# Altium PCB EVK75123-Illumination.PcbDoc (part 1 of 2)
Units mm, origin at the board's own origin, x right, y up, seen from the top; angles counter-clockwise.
Board outline 80 x 50 mm, 4 copper layers (Top Layer, GND, VCC, Bottom Layer), stack 0.976 mm thick; 91 components, 44 nets, 247 pads, 1773 vias.
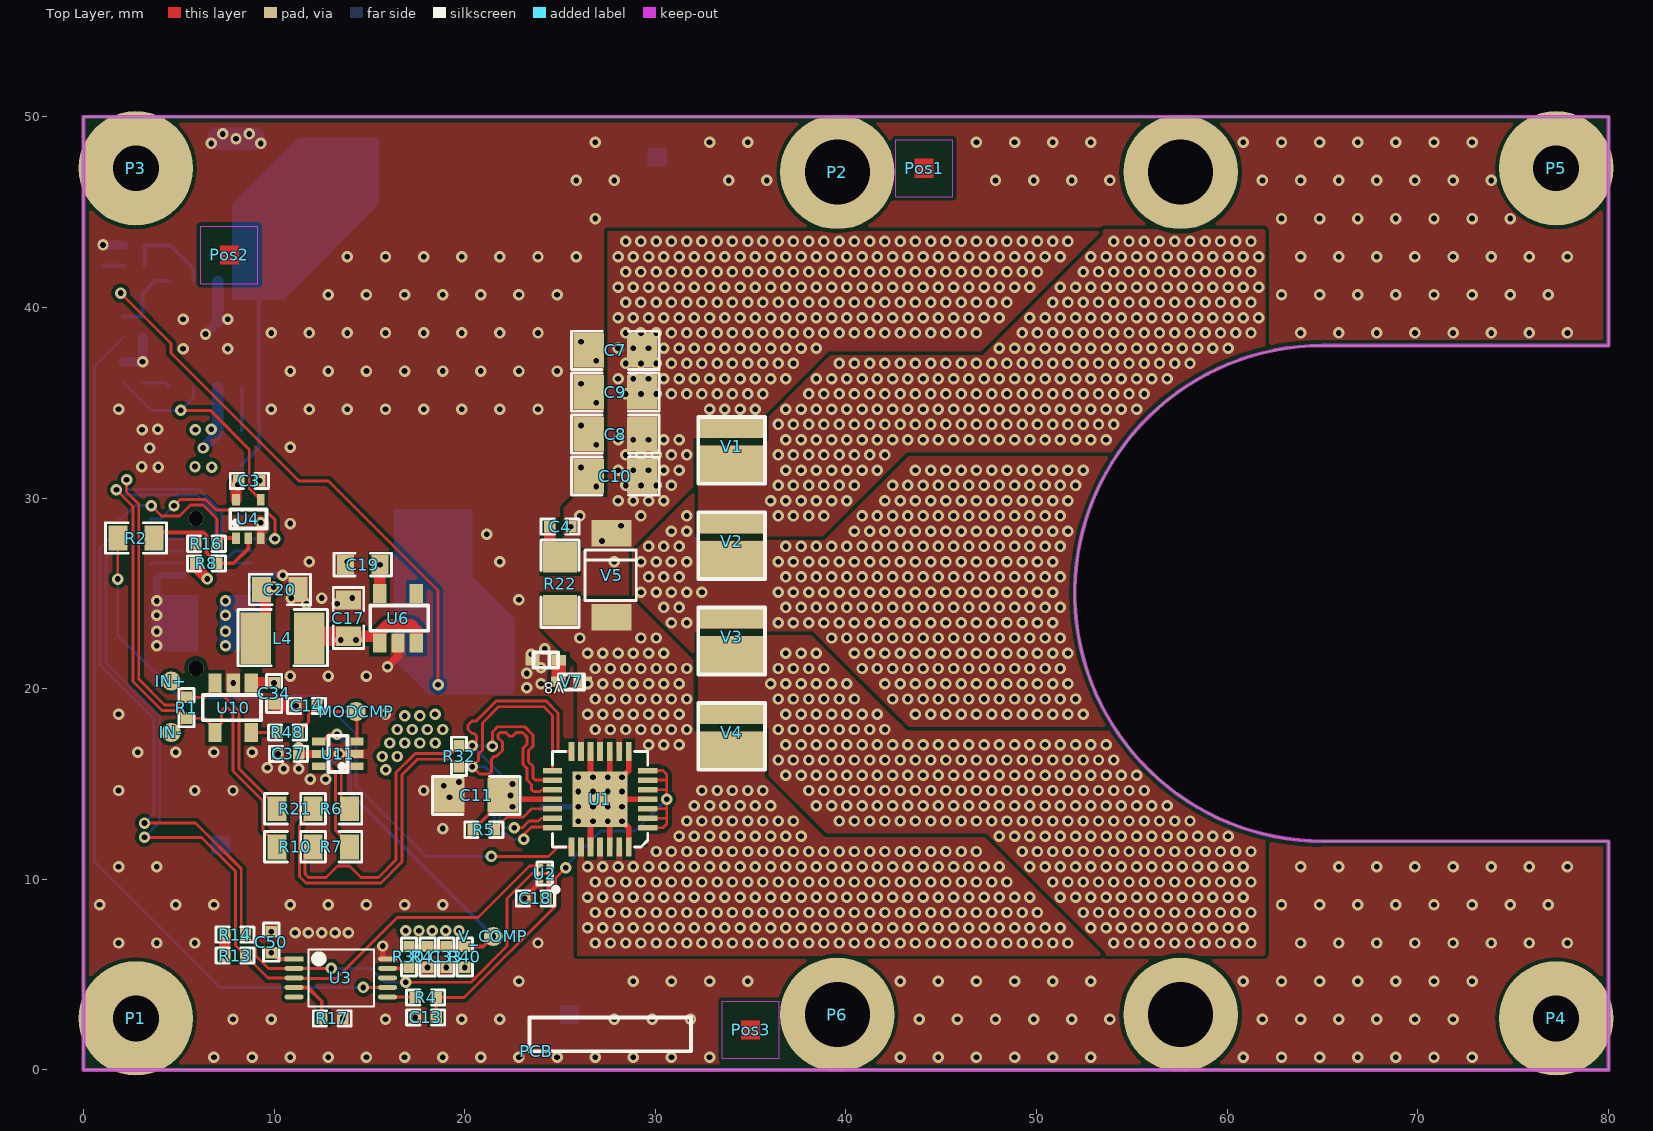
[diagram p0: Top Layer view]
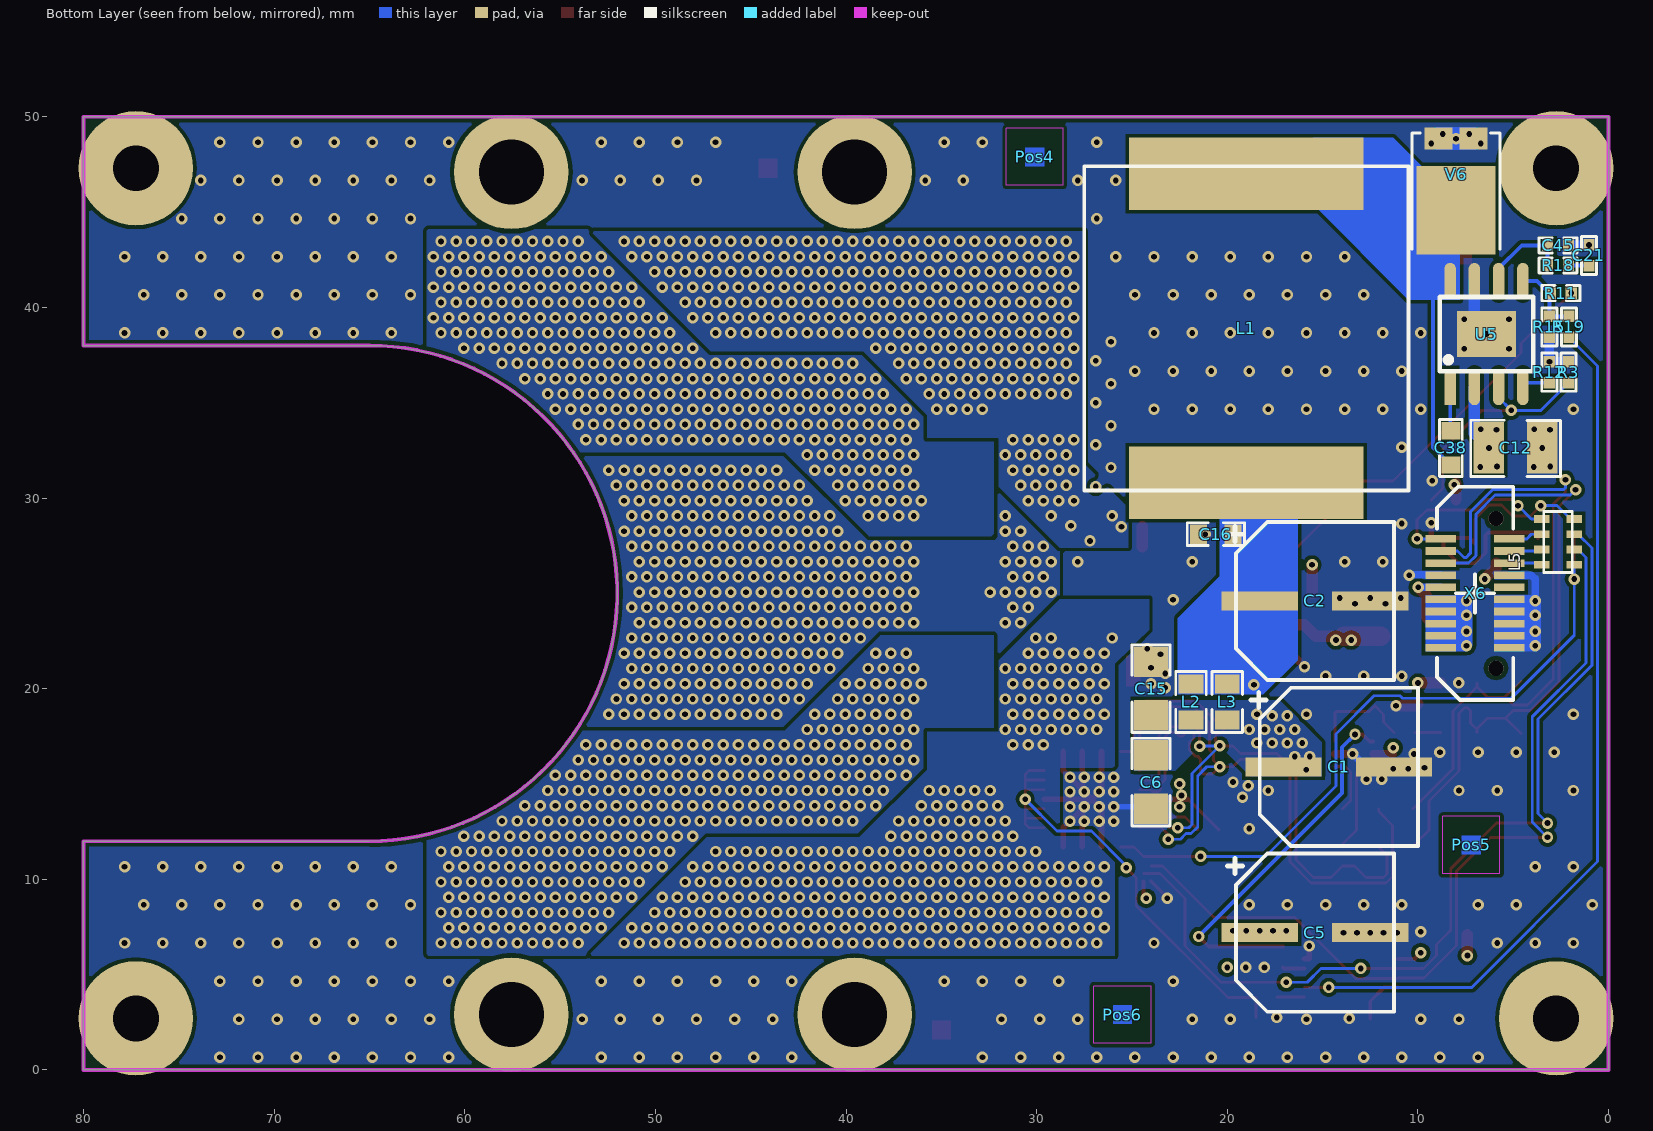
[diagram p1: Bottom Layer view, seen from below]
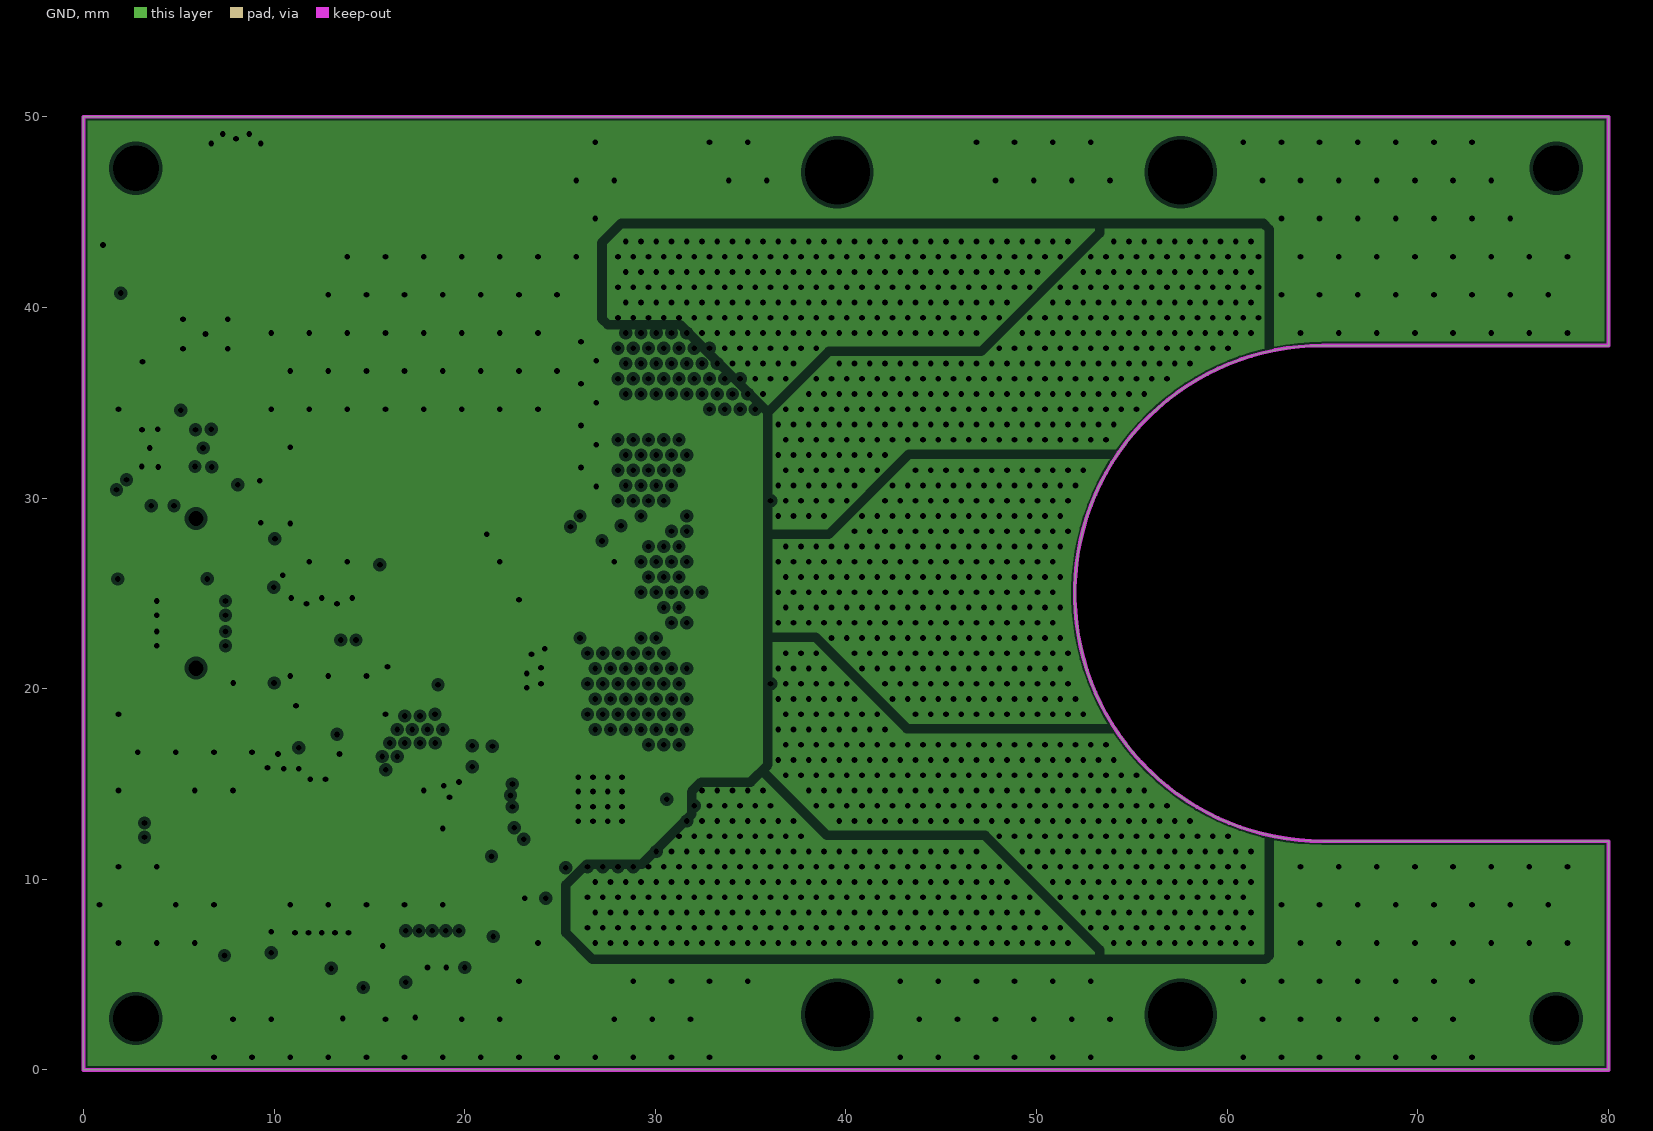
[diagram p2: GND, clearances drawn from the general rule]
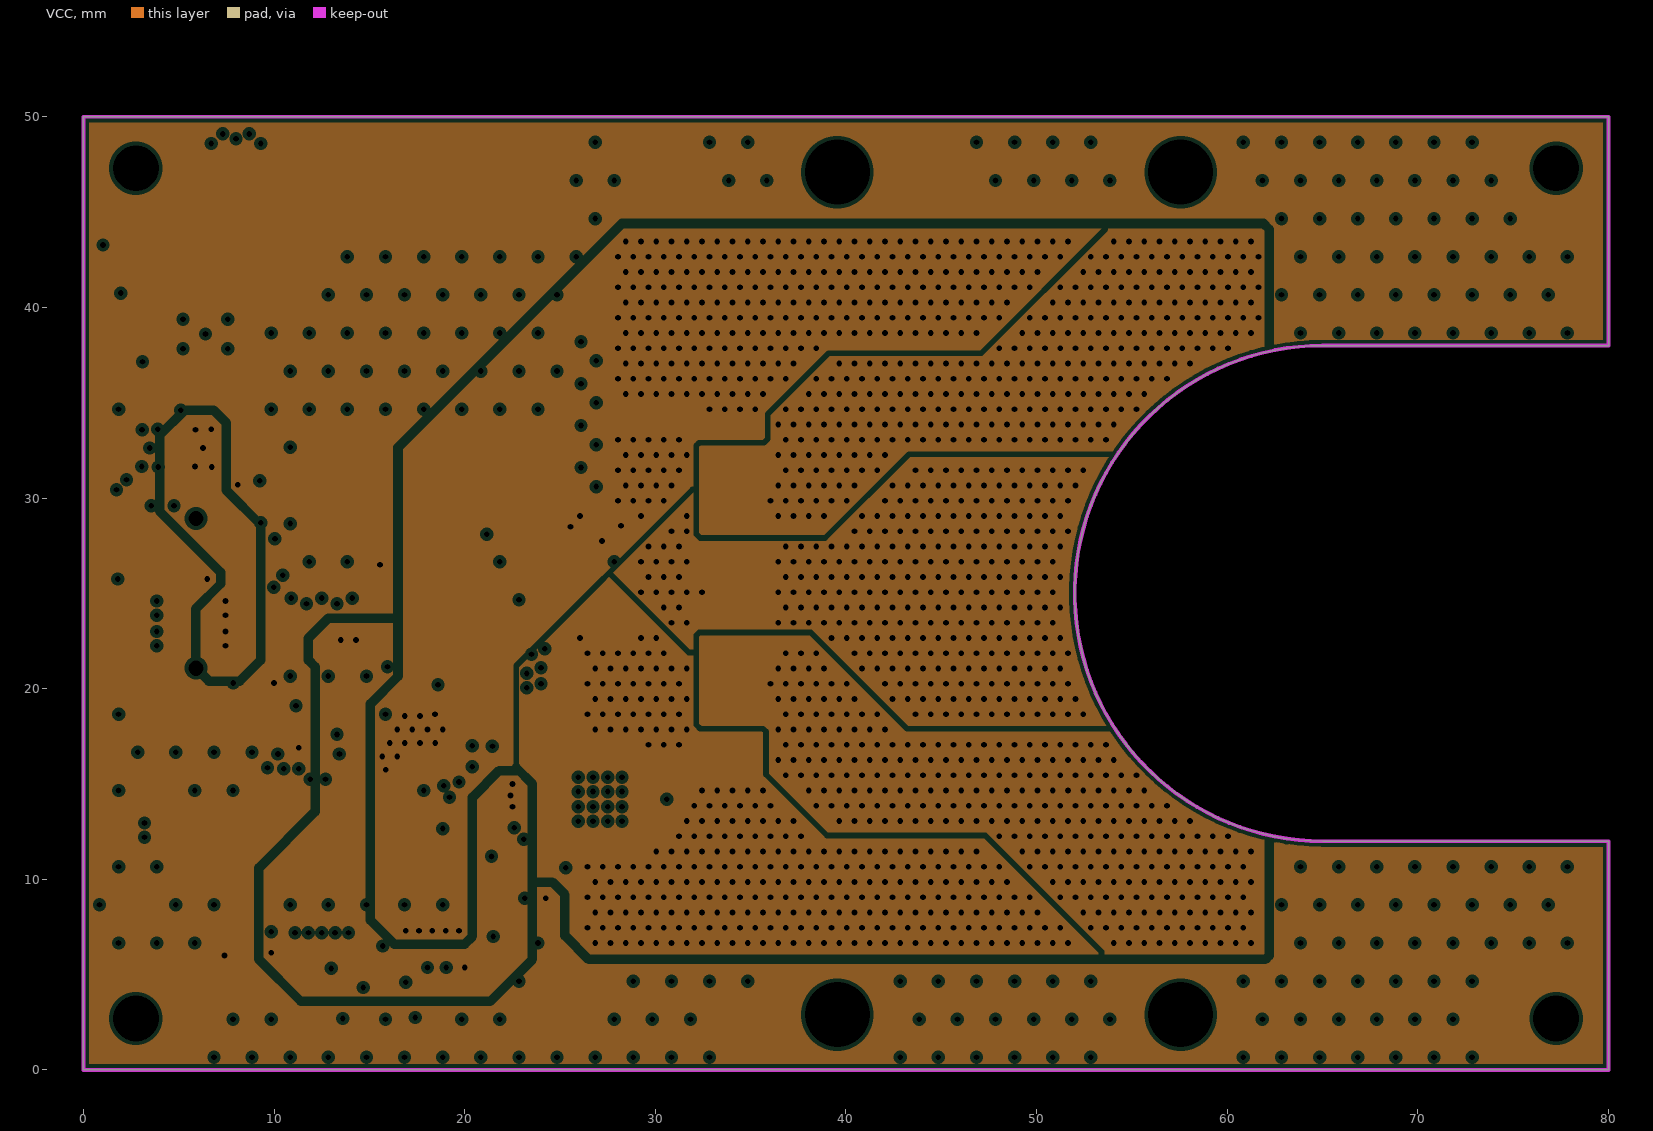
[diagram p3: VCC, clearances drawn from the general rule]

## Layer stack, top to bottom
Top Solder: solder mask 0.05, Solder Resist, Dk 3.5
Top Layer: signal copper 0.039
Dielectric1: prepreg 0.117, FR-4, Dk 4.3
GND: plane copper 0.032, net (Multiple Nets)
Dielectric3: core 0.6, FR-4, Dk 4.47
VCC: plane copper 0.032, net (Multiple Nets)
Dielectric2: prepreg 0.117, FR-4, Dk 4.3
Bottom Layer: signal copper 0.039
Bottom Solder: solder mask 0.05, Solder Resist, Dk 3.5

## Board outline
0,0 0,50 80,50 80,38 65,38 ccw(c65,25) 65,12 80,12 80,0

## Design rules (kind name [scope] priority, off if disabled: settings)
AssemblyTestPointUsage [not (NetPinCount = 1)] p1: allowmultiple=TRUE
AssemblyTestpoint AssemblyTestpoint_Pad [(IsPad And (OnTopLayer)OR (OnBottom))] p1: testpointundercomponent=TRUE minsize=0.8 maxsize=3 preferedsize=0.8 minholesize=0 maxholesize=0 preferedholesize=0 testpointgrid=0.025 usegrid=FALSE gridtolerance=0 allowsidebottom=TRUE minspacing=2.54
AssemblyTestpoint AssemblyTestpoint_Via [(IsVia)] p2: testpointundercomponent=TRUE minsize=0.6 maxsize=0.8 preferedsize=0.8 minholesize=0 maxholesize=0.3 preferedholesize=0.3 testpointgrid=0.025 usegrid=FALSE gridtolerance=0 allowsidebottom=TRUE minspacing=2.54
AssemblyTestpoint AssemblyTestpoint_THT [(IsPad And OnMultiLayer)] p3: testpointundercomponent=TRUE minsize=0.5 maxsize=5 preferedsize=1.524 minholesize=0 maxholesize=3 preferedholesize=0.813 testpointgrid=0.025 usegrid=FALSE gridtolerance=0 allowsidetop=TRUE allowsidebottom=TRUE
AssemblyTestpoint [All] p4: testpointundercomponent=TRUE minsize=1.016 maxsize=2.54 preferedsize=1.524 minholesize=0 maxholesize=1.016 preferedholesize=0.813 testpointgrid=0.025 usegrid=TRUE gridtolerance=0 allowsidetop=TRUE allowsidebottom=TRUE
Clearance Clearance_Hole [All vs not PadIsPlated] p1: gap=0.23
Clearance Clearance_poly [inpolygon] p2: gap=0.2
Clearance [All] p3: gap=0.15
ComponentClearance [not ((InComponent('R7') OR InComponent('R10') OR InComponent('R21') OR InComponent('R6')))] p1: gap=0.1 collisioncheckmode=3 verticalgap=0.1 showdistances=FALSE
DiffPairsRouting [All] p1: maxlimit=0.15 minlimit=0.15 mostfreqgap=0.15 toplayer_minwidth=0.15 toplayer_maxwidth=0.15 toplayer_prefwidth=0.15 bottomlayer_minwidth=0.15 bottomlayer_maxwidth=0.15 bottomlayer_prefwidth=0.15 maxuncoupledlength=17
HoleSize [All] p1: absolutevalues=TRUE maxlimit=3.5 minlimit=0.3 maxpercent=80.000 minpercent=20.000
MatchedLengths MOD [InxSignalClass('MOD')] p1: tolerance=0.2 checknetsindiffpair=FALSE checkdiffpairvsdiffpair=TRUE checkxsignals=TRUE checkothers=TRUE
MatchedLengths MOD_DC [InxSignalClass('All xSignals')] p2: tolerance=0.2 checknetsindiffpair=TRUE checkdiffpairvsdiffpair=FALSE checkxsignals=FALSE checkothers=FALSE
MinimumSolderMaskSliver [All vs IsVia] p1: minsoldermaskwidth=0.1
PlaneClearance PlaneClearance_MH [InPadClass('MH')] p1: clearance=0.5
PlaneClearance [All] p2: clearance=0.2
PlaneConnect [All] p1: planeconnectstyle=Direct reliefexpansion=0.5 reliefentries=4 reliefconductorwidth=0.3 reliefairgap=0.2
PolygonConnect [All] p1: connectstyle=Direct reliefconductorwidth=0.3 reliefentries=4 polygonreliefangle="90 Angle" airgapwidth=0.254
RoutingVias [All] p1: holewidth=0.3 width=0.6 viastyle="Through Hole" minholewidth=0.3 minwidth=0.6 maxholewidth=0.3 maxwidth=0.6
SilkToSolderMaskClearance SilkscreenOverComponentPads [IsPad] p1: minsilkscreentomaskgap=0.254 clearancetoexposedcopper=TRUE
SolderMaskExpansion SolderMaskExpansion_Via [IsVia] p1: expansion=-0.05
SolderMaskExpansion SolderMaskExpansion_ALL [All] p2: expansion=0.05
UnConnectedPin [All] p1:
ViasUnderSMD [All] p1: allowed=TRUE
Width [All] p1: maxlimit=3 minlimit=0.15 preferedwidth=0.15
21 further rules are at their usual default settings.

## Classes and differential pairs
component class U_Power: 24V C1 C2 C5 C6 C12 C15 C16 C19 C21 C38 C45 L1 L2 L3 P1 P2 P3 P4 P5 P6 Pos1 Pos2 Pos3 Pos4 Pos5 Pos6 R3 R11 R12 R15 R18 R19 U5 U6 V6
net class DIFF100: IN_N IN_P MOD1_N MOD1_P MOD_N MOD_P
component class EVK75123-Illumination: C3 C14 C17 C18 C20 C33 C34 C37 C50 IN+ IN- L4 L5 MODCMP PCB R1 R2 R6 R7 R8 R10 R13 R14 R16 R17 R21 R30 R40 R41 R48 U2 U3 U4 U10 U11 V_COMP X6
net class <Power>: 3V3 5V0 17V 24V GND VLD
net class <Hi-Speed>: IN_N IN_P MOD1_N MOD1_P MOD_N MOD_P NAMS2 NAMS3 NAMS4 NAMS5 NAMS6 NAMS7 NAMS8 NAMS9 NAMS10
component class U_Laserdriver: C4 C7 C8 C9 C10 C11 C13 R4 R5 R22 R32 U1 V1 V2 V3 V4 V5 V7 V8
pad class MH: Free-H0 Free-H1 P1-1 P2-1 P3-1 P4-1 P5-1 P6-1
differential pair MOD: +MOD_P -MOD_N
differential pair MOD1: +MOD1_P -MOD1_N
differential pair IN: +IN_P -IN_N

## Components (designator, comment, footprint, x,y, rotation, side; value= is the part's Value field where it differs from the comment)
C1 "Polarized Capicator" ELKO_SMD-8x7 14.15,15.9 r0 bottom
C2 "Polarized Capicator" ELKO_SMD-8x7 15.4,24.6 r0 bottom
C3 "Capacitor non-polarized" 0402 8.7,30.9 r0 top
C4 "Capacitor non-polarized" 0402 25,28.5 r0 top
C5 "Polarized Capicator" ELKO_SMD-8x7 15.4,7.2 r0 bottom
C6 "Capacitor non-polarized" 1206 24,15.1 r270 bottom
C7 "Capacitor non-polarized" 1206 27.9,37.75 r0 top
C8 "Capacitor non-polarized" 1206 27.9,33.35 r0 top
C9 "Capacitor non-polarized" 1206 27.9,35.55 r0 top
C10 "Capacitor non-polarized" 1206 27.9,31.15 r0 top
C11 "Capacitor non-polarized" 1206 20.6,14.4 r0 top
C12 "Capacitor non-polarized" 1210 4.875,32.625 r0 bottom
C13 "Capacitor non-polarized" 0402 17.95,2.75 r0 top
C14 "Capacitor non-polarized" 0402 11.7,19.1 r0 top
C15 "Capacitor non-polarized" 1206 24,20 r270 bottom
C16 "Capacitor non-polarized" 0603 20.6,28.1 r0 bottom
C17 "Capacitor non-polarized" 0805 13.9,23.7 r270 top
C18 "Capacitor non-polarized" 0402 23.7,9 r0 top
C19 "Capacitor non-polarized" 0603 14.65,26.5 r0 top
C20 "Capacitor non-polarized" 0805 10.3,25.2 r180 top
C21 "Capacitor non-polarized" 0402 1.025,42.725 r270 bottom
C33 "Capacitor non-polarized" 0402 19.025,5.925 r270 top
C34 "Capacitor non-polarized" 0402 10,19.75 r270 top
C37 "Capacitor non-polarized" 0402 10.75,16.575 r180 top
C38 "Capacitor non-polarized" 0603 8.275,32.625 r90 bottom
C45 "Capacitor non-polarized" 0402 2.65,43.25 r0 bottom
C50 "Capacitor non-polarized" 0402 9.85,6.7 r270 top
IN+ "Test Pad" PAD_1mm_SMD 4.6,20.4 r0 top
IN- "Test Pad" PAD_1mm_SMD 4.6,17.7 r0 top
L1 "Inductor" VIS-IHLP-6767DZ 19,38.9 r270 bottom
L2 "Ferrite" 0805 21.9,19.3 r270 bottom
L3 "Ferrite" 0805 20,19.3 r270 bottom
L4 "Inductor" 1210 10.45,22.65 r0 top
L5 "Ferrite" 1206_FB-array 2.65,27.7 r90 bottom
MODCMP "Test Pad" PAD_1mm_SMD 14.3,18.8 r90 top
P1 "Test Pad" PAD_M2-5x5#1 2.75,2.7 r270 top locked
P2 "Test Pad" PAD_M2-5x5#2 39.55,47.1 r270 top locked
P3 "Test Pad" PAD_M2-5x5#1 2.75,47.3 r270 top locked
P4 "Test Pad" PAD_M2-5x5#1 77.25,2.7 r270 top locked
P5 "Test Pad" PAD_M2-5x5#1 77.25,47.3 r270 top locked
P6 "Test Pad" PAD_M2-5x5#2 39.55,2.9 r90 top locked
PCB "850-4760" PCB 23.75,1.3 r0 top
Pos1 "Position" Pos-QUADRAT 44.1,47.3 r0 top
Pos2 "Position" Pos-QUADRAT 7.65,42.75 r0 top
Pos3 "Position" Pos-QUADRAT 35,2.1 r0 top
Pos4 "Position" Pos-QUADRAT 30.1,47.9 r180 bottom
Pos5 "Position" Pos-QUADRAT 7.2,11.8 r180 bottom
Pos6 "Position" Pos-QUADRAT 25.5,2.9 r180 bottom
R1 "Resistor" 0402 5.4,19 r270 top
R2 "Resistor" 0805 2.75,27.9 r0 top
R3 "Resistor" 0402 2.1,36.6 r270 bottom
R4 "Resistor" 0402 17.95,3.8 r180 top
R5 "Resistor" 0402 21,12.6 r180 top
R6 "Resistor" 0805 13,13.7 r0 top
R7 "Resistor" 0805 13,11.7 r0 top
R8 "Resistor" 0402 6.45,26.575 r180 top
R10 "Resistor" 0805 11.1,11.7 r180 top
R11 "Resistor" 0402 2.5,40.75 r0 bottom
R12 "Resistor" 0402 3.1,36.6 r90 bottom
R13 "Resistor" 0402 7.95,6 r180 top
R14 "Resistor" 0402 7.95,7.1 r180 top
R15 "Resistor" 0402 3.1,38.975 r90 bottom
R16 "Resistor" 0402 6.45,27.6 r180 top
R17 "Resistor" 0402 13.05,2.7 r180 top
R18 "Resistor" 0402 2.65,42.2 r180 bottom
R19 "Resistor" 0402 2.075,38.975 r270 bottom
R21 "Resistor" 0805 11.1,13.7 r180 top
R22 "Resistor" 1206 25,25.5 r90 top
R30 "Resistor" 0402 17.075,5.925 r90 top
R32 "Resistor" 0402 19.7,16.45 r270 top
R40 "Resistor" 0402 20,5.925 r90 top
R41 "Resistor" 0402 18.05,5.925 r270 top
R48 "Resistor" 0402 10.7,17.7 r0 top
U1 "iC-HG" QFN28-0.5-5-0.9 27.1,14.2 r180 top
U2 "TMP108" BGA6-0.4-0.25-1.2x0.8 24.2,10.3 r180 top
U3 "MCP4728" MSOP10-0.5-5 13.5,4.825 r0 top
U4 "Single-Gate Dual-Input AND-Logic-Gate" SOT353-0.65--2.6 8.65,28.9 r90 top
U5 "TPS54061" PSO8-1.27-7.3 6.4,38.6 r90 bottom
U6 "LP2985" SOT23-5-0.95--3.6 16.5,23.7 r90 top
U10 "FIN1002" SOT23-5-0.95--3.6 7.85,19 r270 top
U11 "ADCMP604" SOT363-0.65--2.6 13.35,16.575 r180 top
V1 "Light Emitting Diode" PCW-SMT-2 34,32.5 r0 top
V2 "Light Emitting Diode" PCW-SMT-2 34,27.5 r0 top
V3 "Light Emitting Diode" PCW-SMT-2 34,22.5 r0 top
V4 "Light Emitting Diode" PCW-SMT-2 34,17.5 r0 top
V5 "Schottky Diode" SOD128 27.7,26.5 r270 top
V6 "Default Diode" TO-277-3 8,46.1 r0 bottom
V7 "Z-Diode" SOD523 25.6,20.35 r180 top
V8 "Z-Diode" SOD523 24.25,21.5 r180 top
V_COMP "Test Pad" PAD_1mm_SMD 21.5,7 r90 top
X6 "CON20(1-2)" SAM-LSS-110-02-F-DV-A 7,25 r270 bottom locked

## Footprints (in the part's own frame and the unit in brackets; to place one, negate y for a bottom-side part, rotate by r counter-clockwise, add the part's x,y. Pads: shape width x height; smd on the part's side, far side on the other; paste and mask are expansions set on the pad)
0402 [mm]
  rect 0.6x0.6 smd: 1(-0.55,0) 2(0.55,0)
  silkscreen extent -1,-0.4 1,0.4, body extent -0.51,-0.25 0.51,0.25, height 0.41
0603 [mm]
  rect 0.9x1 smd: 1(-0.9,0) 2(0.9,0)
  silkscreen extent -1.5,-0.6 1.5,0.6, body extent -0.89,-0.38 0.89,0.38, height 0.76
0805 [mm]
  rect 1x1.3 smd: 1(-0.95,0) 2(0.95,0)
  silkscreen extent -1.6,-0.8 1.6,0.8, body extent -1,-0.51 1,0.51, height 1
1206 [mm]
  rect 1.6x1.8 smd: 1(-1.4,0) 2(1.4,0)
  silkscreen extent -2.3,-1 2.3,1, body extent -1.45,-0.76 1.45,0.76, height 1.51
1206_FB-array [mm]
  rect 0.4x0.8 smd: 1(-1.2,-0.85) 2(-0.4,-0.85) 3(0.4,-0.85) 4(1.2,-0.85) 5(1.2,0.85) 6(0.4,0.85) 7(-0.4,0.85) 8(-1.2,0.85)
  silkscreen extent -1.6,-0.75 1.6,0.75, body extent -1.6,-0.76 1.6,0.76, height 0.8
1210 [mm]
  rect 1.6x2.7 smd: 1(-1.4,0) 2(1.4,0)
  silkscreen extent -2.35,-1.45 2.35,1.5, body extent -1.61,-1.26 1.61,1.3, height 2.51
BGA6-0.4-0.25-1.2x0.8 [mm]
  round 0.25 smd: A1(-0.2,0.4) A2(0.2,0.4) B1(-0.2,0) B2(0.2,0) C1(-0.2,-0.4) C2(0.2,-0.4)
  silkscreen extent -0.69,-0.6 0.4,0.96, body extent -0.4,-0.6 0.4,0.6, height 0.63
ELKO_SMD-8x7 [mm] "Elko"
  rect 4x1 smd: 1(2.9,0) 2(-2.9,0)
  silkscreen extent -4.15,-4.15 4.6,4.15, body extent -4.5,-4.15 4.5,4.15, height 6.9
MSOP10-0.5-5 [mm]
  rect 1x0.25 smd: 1(-2.45,1)
  oval 1x0.25 smd: 2(-2.45,0.5) 3(-2.45,0) 4(-2.45,-0.5) 5(-2.45,-1) 6(2.45,-1) 7(2.45,-0.5) 8(2.45,0) 9(2.45,0.5) 10(2.45,1)
  silkscreen extent -1.7,-1.5 1.74,1.5, body extent -2.58,-1.5 2.58,1.5, height 1.11
PAD_1mm_SMD [mm]
  round 1 smd paste-1: 1(0,0)
PAD_M2-5x5#1 [mm]
  round 6 hole 2.4 paste-1.5: 1(0,0)
  body extent -1.9,-1.9 1.9,1.9, height 2
PAD_M2-5x5#2 [mm]
  round 6 hole 3.4 paste-1.5: 1(0,0)
  body extent -1.9,-1.9 1.9,1.9, height 2
PCB [mm]
  rect 0.2x0.2 on Top Overlay mask+0.05: 1(0,-0.325)
  silkscreen extent -0.35,-0.33 8.13,1.45
PCW-SMT-2 [mm]
  rect 3.5x1.1 smd mask+0.05: 1(0,1.2)
  rect 3.5x2 smd mask+0.05: 2(0,-0.75)
  Top Layer pour cut-out: -1.75,0.65 -1.75,0.25 1.75,0.25 1.75,0.65
  silkscreen extent -1.75,-1.75 1.75,1.75, body extent -1.75,-1.75 1.75,1.75, height 2
Pos-QUADRAT [mm] "Positioning mark cross"
  Top Layer region: -0.5,-0.5 0.5,-0.5 0.5,0.5 -0.5,0.5
  Top Layer keep-out lines w0: -1.5,-1.5 1.5,-1.5 1.5,1.5 -1.5,1.5 -1.5,-1.5
PSO8-1.27-7.3 [mm]
  rect 2.41x3.1 smd paste-3 mask-3: 0(0,0)
  rect 1.9x0.6 smd: 1(-2.78,1.905)
  oval 1.9x0.6 smd: 2(-2.78,0.635) 3(-2.78,-0.635) 4(-2.78,-1.905) 5(2.78,-1.905) 6(2.78,-0.635) 7(2.78,0.635) 8(2.78,1.905)
  silkscreen extent -1.95,-2.45 1.95,2.45, body extent -1.95,-2.45 1.95,2.45, height 1.7
QFN28-0.5-5-0.9 [mm]
  rect 2.9x2.9 smd paste-2: 0(0,0)
  rect 1x0.3 smd paste-0.025: 1(-2.5,1.5) 2(-2.5,1) 3(-2.5,0.5) 4(-2.5,0) 5(-2.5,-0.5) 6(-2.5,-1) 7(-2.5,-1.5) 15(2.5,-1.5) 16(2.5,-1) 17(2.5,-0.5) 18(2.5,0) 19(2.5,0.5) 20(2.5,1) 21(2.5,1.5)
  rect 0.3x1 smd paste-0.025: 8(-1.5,-2.5) 9(-1,-2.5) 10(-0.5,-2.5) 11(0,-2.5) 12(0.5,-2.5) 13(1,-2.5) 14(1.5,-2.5) 22(1.5,2.5) 23(1,2.5) 24(0.5,2.5) 25(0,2.5) 26(-0.5,2.5) 27(-1,2.5) 28(-1.5,2.5)
  silkscreen extent -2.5,-2.5 2.5,2.5, body extent -2.5,-2.5 2.5,2.5, height 0.91
SAM-LSS-110-02-F-DV-A [mm] "SAM-LSS-105-01-F-DV-A"
  rect 0.4x1.6 smd: 1(2.857,-1.8) 2(2.858,1.8) 3(2.222,-1.8) 4(2.223,1.8) 5(1.587,-1.8) 6(1.588,1.8) 7(0.952,-1.8) 8(0.953,1.8) 9(0.317,-1.8) 10(0.318,1.8) 11(-0.318,-1.8) 12(-0.317,1.8) 13(-0.953,-1.8) 14(-0.952,1.8) 15(-1.588,-1.8) 16(-1.587,1.8) 17(-2.223,-1.8) 18(-2.222,1.8) 19(-2.858,-1.8) 20(-2.857,1.8)
  round 0.8 hole 0.8 unplated: A1(3.925,1.1) A2(-3.925,1.1)
  silkscreen extent -5.59,-2 5.59,2, body extent -5.57,-2.3 5.53,2.3, height 7.45
SOD128 [mm]
  rect 1.4x2.1 smd: 1(2.75,0) 2(-1.65,0)
  silkscreen extent -0.77,-1.4 1.88,1.3, body extent -2.07,-1.4 3.18,1.3, height 1.11
SOD523 [mm]
  rect 0.75x0.55 smd: 1(0.7,0) 2(-0.7,0)
  silkscreen extent -0.65,-0.4 0.65,0.4, body extent -0.8,-0.4 0.8,0.4, height 0.6
SOT23-5-0.95--3.6 [mm]
  rect 1x0.7 smd: 1(-1.3,0.95) 2(-1.3,0) 3(-1.3,-0.95) 4(1.3,-0.95) 5(1.3,0.95)
  silkscreen extent -0.67,-1.59 0.66,1.46, body extent -1.45,-1.45 1.35,1.45, height 1.09
SOT353-0.65--2.6 [mm]
  rect 0.6x0.4 smd: 1(-1,0.65) 2(-1,0) 3(-1,-0.65) 4(1,-0.65) 5(1,0.65)
  silkscreen extent -0.5,-0.95 0.5,0.95, body extent -1.1,-0.95 1.1,0.95, height 0.95
SOT363-0.65--2.6 [mm]
  rect 0.7x0.4 smd: 1(-1,0.65) 2(-1,0) 3(-1,-0.65) 4(1,-0.65) 5(1,0) 6(1,0.65)
  silkscreen extent -0.5,-0.95 0.5,0.95, body extent -1.1,-0.95 1.1,0.95, height 0.95
TO-277-3 [mm] "TO-277-3 / PowerDI"
  rect 1.45x1.15 smd: 1(-0.92,-2.75) 3(0.92,-2.75)
  rect 4.15x4.65 smd: 2(0,1)
  silkscreen extent -2.3,-3.05 2.3,3.05, body extent -2.03,-3.3 2.02,3.3, height 1.17
VIS-IHLP-6767DZ [mm] "Speicherdrossel"
  rect 3.8x12.3 smd: 1(-8.1,0) 2(8.1,0)
  silkscreen extent -8.5,-8.5 8.5,8.5, body extent -8.61,-8.58 8.56,8.6, height 3.91

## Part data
C1 C2 C5: library part 15423dca-9b42-4089-8a58-6a30d5d5cf06, "C-68u-35V-20%-44mR"
C3 C13 C18 C33 C34 C37 C50: library part 54C877D5-E705-4C14-AD3D-8F4F7B57D597, "C-0402-100n-16V-10%"
C4: library part 0097ADC0-227E-4059-A51E-B4508658C31A, "C-0402-270p-50V-5%"
C6 C7 C8 C9 C10 C11 C15: library part 6574bd8d-1f7f-4017-8c13-fc1ff6c564f2, "C-1206-100n-50V-5%"
C12: library part c11633e3-883f-4ea1-bab5-305a930c1712, "C-1210-2u2-100V-X7R"
C14 C45: library part 11FE33DF-B8B2-497C-ADE2-798944BCF4BE, "C-0402-15p-50V-5%"
C16 C38: library part F4F417EB-80BB-43BD-9294-E69FEC10CC02, "C-0603-100n-50V-10%"
C17 C20: library part 47BE2105-E645-4B7D-88B5-189FA600BE5F, "C-0805-10u-10V-10%"
C19: library part 62C539F0-6F12-4C64-8973-B77ABBA35E0D, "C-0603-1u-25V-10%"
C21: library part 0D03DA8E-6E9D-48FA-B2D5-DDC88D2A4CF2, "C-0402-18n-16V-10%"
IN+ IN-: library part D58E77CC-74E0-4972-9B60-0D1F1EE06ED8, "Test Pad 1mm"
L1: library part c927bdf3-e195-4335-ae34-2dcccbc64859, "L-VIS-IHLP-6767-22u-6.2A-20%"
L2 L3: library part 4558f3ef-a2ca-4732-a97e-33e36c5aad12, "F-0805-120Z-5A"
L4: library part 5A39A3C7-8FFF-4AB6-80A4-55595FBEE935, "L-1210-10u-450mA"
L5: library part 17bc767e-4081-41c9-96a1-8705f6a55660, "F-1206array-600Z-100mA"
MODCMP V_COMP: library part 291B522A-DD06-443D-9DB9-AAD5D6CD8DE2, "PAD 1x2.54"
P1 P2 P3 P4 P5 P6: library part d95d2f47-965b-47b2-ac00-e8d5b9325de3, "M2 Mounting Hole 5x5"
PCB: library part b0395311-27a9-4c03-a85f-d7f544fec484, "PCB_EVK75123-Illumination V1.1"
Pos1 Pos2 Pos3 Pos4 Pos5 Pos6: library part A97550DC-E5EA-465D-9168-34E3565B8720, "Pos-QUADRAT-3mm"
R1 R4 R32 R48: library part 5753A1E5-EBD2-4BBF-8026-C9AE8047C4EC, "R-0402-100R-1%"
R2 R6 R7 R10 R21: library part 96878DCE-2E24-48BD-A958-A9B2669E8EA5, "R-0805-0R-5%"
R3 R15 R18: library part A4A7BB00-465D-4C1E-8319-4836672F5686, "R-0402-18k-1%"
R5 R8 R13 R14 R16 R17 R40 R41: library part 87ff11f6-a19c-4fd3-a86d-d729e9959c04, "R-0402-3k6-1%"
R11 R12: library part 0499915E-9BF4-4C7F-8B08-D182950F3B89, "R-0402-330k-1%"
R19: library part 57b0607b-283e-4831-8b97-1b038861c010, "R-0402-130k-1%"
R22: library part 1a6a65a5-8098-42a8-a07d-6c7b13c9a3e6, "R-1206-1R-1%-0.5W"
R30: library part 301741e4-a97d-4c83-8d7a-1b789196cb5a, "R-0402-1k5-1%"
U1: library part 900fa9a9-c7df-41b9-b82b-983ec3f9771c, "3 A LASER SWITCH"
U2: library part 1756c951-2cf8-4c64-a988-e546f59afa21, "±1°C Accurate 12bit Digital Temperature Sensor"
U3: library part 7021478d-2d84-431d-b8be-32d6dfcf2c4d, "12-Bit Digital-to-Analog Converter with EEPROM Memory"
U4: library part B349E2D1-8349-4508-822A-E73FFBEB3634, "74AHC1G08"
U5: library part 83e8cd34-1e26-4937-9357-3a852f02699a, "4.5 V to 60 V Input, 5 A, Step Down DC-DC Converter with Eco-mode"
U6: library part 595174d6-4f0f-4a85-858e-941119242838, "3.3V, Micropower 100 mA Low-Noise Ultra Low-Dropout Regulator"
U10: library part b52cc92d-fdf7-47cb-bf43-294665300321, "LVDS differential line driver"
U11: library part cead70f7-3ca7-495c-bd07-28229ce7803b, "Rail-to-Rail, Very Fast, 2.5 V to 5.5 V, Single-Supply LVDS Comparator"
V1 V2 V3 V4: library part 85e564f8-3a71-4d92-9828-a8b6dfe11ab7, "VCSEL Array Laser Diode"
V5: library part 39a5ee8a-d88f-425e-8062-ede2c4d3764b, "PMEG3050EP"
V6: library part a2494603-b754-4332-b2d6-676b3f1482f6, "12A, 100V Ultra-Low Vf Schottky Rectifier"
V7 V8: library part CC9D59A8-5C7A-4322-9DFB-934945E300CD, "PESD5V0S1UB - 5.0V"
X6: library part 379f8e5c-a288-4eeb-8f71-ca0e0501eadd, "High speed hermaphrodotoc strip"

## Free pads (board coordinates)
  round 6 hole 3.4 unplated: H0(57.55,47.1) H1(57.55,2.9)

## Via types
v1: diameter 0.6, hole 0.3, Top Layer to Bottom Layer, tented both sides, 1773 vias

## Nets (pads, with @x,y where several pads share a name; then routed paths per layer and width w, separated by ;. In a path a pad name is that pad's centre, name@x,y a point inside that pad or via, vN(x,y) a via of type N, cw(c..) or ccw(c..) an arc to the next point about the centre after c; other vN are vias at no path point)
3V3: C3.1 C18.2 C19.2 C34.1 C37.1 R8.2 R13.2 R14.2 U2.A1 U4.5 U6.5 U10.1 U11.5 | length 7.7
  Top Layer w0.2: v1(24.25,9) 24.4,9.15 U2.A1@24.4,9.9
  Top Layer w0.4: C37.1@11.3,16.575 U11.5@12.35,16.575
  Top Layer w0.6: R8.2@5.9,26.575 5.9,26.358 v1(6.5,25.758) ; v1(7.4,6) R14.2@7.4,7.1 ; U4.5@8,29.9 C3.1@8,30.75 ; U10.1@8.8,20.3 v1(10,20.3) ; U6.5@15.55,25 v1(15.55,26.5)
  other v1: 11.3,16.9 8.1,30.7
5V0: C11.2 C17.2 C50.2 L4.2 R5.2 R40.1 U1.18 U3.1 U6.1 U6.3 | length 12.7
  Top Layer w0.2: v1(9.85,6.15) 10.175,5.825 U3.1@11.05,5.825 ; R5.2@20.45,12.6 C11.2@22.1,14.25
  Top Layer w0.3: C11.2@22.1,14.2 U1.18@24.6,14.2
  Top Layer w0.6: C17.2@13.9,22.75 15.364,22.75 15.964,23.35 17.2,23.35 17.45,23.1 U6.3@17.45,22.4
  Top Layer w1: L4.2@11.95,22.75 C17.2@13.9,22.75
  other v1: 20,5.375 22.5,13.8 22.4,14.4 22.5,15 13.5,22.55 14.3,22.55
17V: C2.1 C16.1 L1.2 L2.1 L3.1 R11.1 | length 28.4
  Top Layer w0.15: v1(1.95,40.75) 4.6,38.1 4.6,37.6 11.3,30.9 12.85,30.9 18.6,25.15 v1(18.6,20.2)
24V: C12.2 U5.2 X6.1 X6.3 X6.5 X6.7 X6.9 | length 3.5
  Bottom Layer w0.6: v1(6.275,32.625) 7.035,33.385 U5.2@7.035,35.82
  other v1: 7.45,22.25 7.45,23 7.45,23.85 7.45,24.6 6.725,31.625 5.85,31.65 5.875,33.575 6.7,33.6
FB17V: R11.2 R15.2 R19.1 U5.5 | length 3.9
  Bottom Layer w0.2: R19.1@2.075,39.525 R15.2@3.1,39.525 3.1,40.725 3.125,40.75 3.755,41.38 U5.5@4.495,41.38
GND: C1.2 C2.2 C3.2 C5.2 C6.2 C7.1 C8.1 C9.1 C10.1 C11.1 C12.1 C13.1 C14.1 C15.1 C16.2 C17.1 C18.1 C19.1 C20.1 C21.1 C33.2 C34.2 C37.2 C45.1 C50.1 R3.1 R12.2 R15.1 R16.2 R17.1 R41.2 U1.0 U1.4 U1.8 U1.10 U1.12 U1.24 U1.26 U1.28 U2.A2 U3.10 U4.3 U5.0 U5.7 U6.2 U10.2 U11.2 V6.1 V6.3 V8.1 X6.2 X6.4 X6.6 X6.8 X6.10 X6.13 X6.14 | length 40.2
  Top Layer w0.2: v1(23.15,9) 23.15,9.05 U2.A2@24,9.9
  Top Layer w0.3: U4.3@9.3,27.9 v1(9.3,28.7) ; v1(15.7,6.5) 15.7,5.825 U3.10@15.95,5.825 ; U1.24@26.6,11.7 26.6,13.7 U1.0@27.1,14.2 ; U1.12@26.6,16.7 26.6,14.7 U1.0@27.1,14.2 ; U1.26@27.6,11.7 U1.0@27.6,13.7 ; U1.10@27.6,16.7 U1.0@27.6,14.7 ; U1.28@28.6,11.7 28.6,12.7 U1.0@27.6,13.7 ; U1.8@28.6,16.7 28.6,15.7 U1.0@27.6,14.7 ; U1.4@29.6,14.2 U1.0@27.1,14.2 ; U1.0@27.1,14.2 U1.0@27.6,14.7 ; U1.0@27.1,14.2 U1.0@27.6,13.7
  Top Layer w0.4: v1(13.425,16.575) U11.2@14.35,16.575 ; v1(15.95,21.15) 16.5,21.7 U6.2@16.5,22.4
  Top Layer w0.6: C34.2@10,19.2 10.1,19.1 v1(11.15,19.1)
  Bottom Layer w0.3: C6.2@24,13.7 24.1,13.8 v1(25.95,13.8)
  Bottom Layer w0.4: v1(3.85,24.6) 3.85,25.75 4.053,25.953 X6.14@5.2,25.953 ; X6.13@8.8,25.953 8.815,25.967 10.432,25.967 v1(10.447,25.953) ; C1.2@12.75,15.9 v1(13.425,16.575)
  Bottom Layer w0.5: v1(1.025,43.275) 1.05,43.25 C45.1@2.1,43.25 ; R3.1@2.1,37.15 v1(3.1,37.15) R15.1@3.1,38.425 ; v1(6.4,38.6) U5.0@7.035,39.235
  Bottom Layer w0.6: U5.0@7.035,39.235 U5.7@7.035,41.38
  Bottom Layer w1.2: V6.1@7.08,48.85 V6.3@8.92,48.85
  other v1: 6.843,0.658 8.843,0.658 10.843,0.658 12.843,0.658 14.843,0.658 16.843,0.658 18.843,0.658 20.843,0.658 22.843,0.658 24.843,0.658 26.843,0.658 28.843,0.658 30.843,0.658 32.843,0.658 42.843,0.658 44.843,0.658 46.843,0.658 48.843,0.658 50.843,0.658 52.843,0.658 60.843,0.658 62.843,0.658 64.843,0.658 66.843,0.658 68.843,0.658 70.843,0.658 72.843,0.658 7.843,2.658 9.843,2.658 15.843,2.658 19.843,2.658 21.843,2.658 27.843,2.658 29.843,2.658 31.843,2.658 43.843,2.658 45.843,2.658 47.843,2.658 49.843,2.658 51.843,2.658 53.843,2.658 61.843,2.658 63.843,2.658 65.843,2.658 67.843,2.658 69.843,2.658 71.843,2.658 13.6,2.7 17.4,2.75 22.843,4.658 28.843,4.658 30.843,4.658 32.843,4.658 34.843,4.658 42.843,4.658 44.843,4.658 46.843,4.658 48.843,4.658 50.843,4.658 52.843,4.658 60.843,4.658 62.843,4.658 64.843,4.658 66.843,4.658 68.843,4.658 70.843,4.658 72.843,4.658 18.05,5.375 19.025,5.375 1.843,6.658 3.843,6.658 5.843,6.658 23.843,6.658 63.843,6.658 65.843,6.658 67.843,6.658 69.843,6.658 71.843,6.658 73.843,6.658 75.843,6.658 77.843,6.658 11.1,7.2 11.8,7.2 12.5,7.2 13.2,7.2 13.9,7.2 9.85,7.25 0.843,8.658 4.843,8.658 6.843,8.658 10.843,8.658 12.843,8.658 14.843,8.658 16.843,8.658 18.843,8.658 62.843,8.658 64.843,8.658 66.843,8.658 68.843,8.658 70.843,8.658 72.843,8.658 74.843,8.658 76.843,8.658 1.843,10.658 3.843,10.658 63.843,10.658 65.843,10.658 67.843,10.658 69.843,10.658 71.843,10.658 73.843,10.658 75.843,10.658 77.843,10.658 18.843,12.658 25.95,13.05 26.725,13.05 27.5,13.05 28.25,13.05 26.725,13.8 27.5,13.8 28.25,13.8 19.2,14.3 25.95,14.6 26.725,14.6 27.5,14.6 28.25,14.6 1.843,14.658 5.843,14.658 7.843,14.658 17.843,14.658 18.9,14.9 19.7,15.1 11.9,15.25 12.7,15.25 25.95,15.35 26.725,15.35 27.5,15.35 28.25,15.35 10.5,15.8 11.3,15.8 9.65,15.85 10.2,16.575 2.843,16.658 4.843,16.658 6.843,16.658 8.843,16.658 1.843,18.658 15.843,18.658 23.25,20.05 24,20.25 7.85,20.3 10.843,20.658 12.843,20.658 14.843,20.658 23.25,20.8 24,21.1 23.5,21.8 24.2,22.1 3.85,22.25 3.85,23 3.85,23.85 11.7,24.45 13.3,24.45 22.843,24.658 10.9,24.75 12.5,24.75 14.1,24.75 11.843,26.658 13.843,26.658 21.843,26.658 27.843,26.658 21.15,28.1 10.843,28.658 26.9,30.6 9.25,30.9 26.1,31.6 3.925,31.625 3.05,31.65 3.475,32.625 10.843,32.658 26.9,32.8 3.075,33.575 3.9,33.6 26.1,33.8 1.843,34.658 9.843,34.658 11.843,34.658 13.843,34.658 15.843,34.658 17.843,34.658 19.843,34.658 21.843,34.658 23.843,34.658 26.9,35 26.1,36 10.843,36.658 12.843,36.658 14.843,36.658 16.843,36.658 18.843,36.658 20.843,36.658 22.843,36.658 24.843,36.658 26.9,37.2 5.225,37.825 7.575,37.825 26.1,38.2 9.843,38.658 11.843,38.658 13.843,38.658 15.843,38.658 17.843,38.658 19.843,38.658 21.843,38.658 23.843,38.658 63.843,38.658 65.843,38.658 67.843,38.658 69.843,38.658 71.843,38.658 73.843,38.658 75.843,38.658 77.843,38.658 5.225,39.375 7.575,39.375 12.843,40.658 14.843,40.658 16.843,40.658 18.843,40.658 20.843,40.658 22.843,40.658 24.843,40.658 62.843,40.658 64.843,40.658 66.843,40.658 68.843,40.658 70.843,40.658 72.843,40.658 74.843,40.658 76.843,40.658 13.843,42.658 15.843,42.658 17.843,42.658 19.843,42.658 21.843,42.658 23.843,42.658 25.843,42.658 63.843,42.658 65.843,42.658 67.843,42.658 69.843,42.658 71.843,42.658 73.843,42.658 75.843,42.658 77.843,42.658 26.843,44.658 62.843,44.658 64.843,44.658 66.843,44.658 68.843,44.658 70.843,44.658 72.843,44.658 74.843,44.658 25.843,46.658 27.843,46.658 33.843,46.658 35.843,46.658 47.843,46.658 49.843,46.658 51.843,46.658 53.843,46.658 61.843,46.658 63.843,46.658 65.843,46.658 67.843,46.658 69.843,46.658 71.843,46.658 73.843,46.658 6.7,48.6 9.3,48.6 26.843,48.658 32.843,48.658 34.843,48.658 46.843,48.658 48.843,48.658 50.843,48.658 52.843,48.658 60.843,48.658 62.843,48.658 64.843,48.658 66.843,48.658 68.843,48.658 70.843,48.658 72.843,48.658 8,48.85 7.3,49.1 8.7,49.1
I2C.SCL: L5.3 R14.1 U2.B1 U2.B2 U3.2 | length 47.7
  Top Layer w0.15: v1(3.2,12.95) 5.874,12.95 8.275,10.549 8.275,7.325 R14.1@8.5,7.1 9.025,6.575 9.025,6 9.7,5.325 U3.2@11.05,5.325 v1(13,5.325) ; v1(16.9,4.6) 20.332,4.6 22.225,6.493 22.225,8.993 23.532,10.3 U2.B2@24,10.3 U2.B1@24.4,10.3
  Bottom Layer w0.15: L5.3@1.8,28.1 1.6,28.1 0.875,27.375 0.875,21.225 3.7,18.4 3.7,13.45 v1(3.2,12.95) ; v1(13,5.325) 15.075,5.325 15.8,4.6 v1(16.9,4.6)
I2C.SDA: L5.2 R13.1 U2.C2 U3.3 | length 45.6
  Top Layer w0.15: v1(3.2,12.2) 6.2,12.2 7.975,10.425 7.975,6.525 R13.1@8.5,6 9.675,4.825 U3.3@11.05,4.825 11.075,4.8 13.258,4.8 16.458,8 20.7,8 23.4,10.7 U2.C2@24,10.7
  Bottom Layer w0.15: L5.2@1.8,27.3 1.6,27.3 1.175,26.875 1.175,21.349 4,18.524 4,13 v1(3.2,12.2)
IN_N: IN-.1 R1.2 R10.2 U10.4 X6.15 | length 36.9
  Top Layer w0.15: v1(1.729,30.429) 2.6,29.558 2.6,20.376 4.126,18.85 5,18.85 R1.2@5.4,18.45 ; IN-.1@4.6,17.65 R1.2@5.4,18.45 ; U10.4@6.9,17.7 U10.4@6.9,17.85 ; R10.2@10.15,11.7 10.15,11.85 9.425,12.575 9.425,14.101 7.85,15.676 7.85,18.708 7.558,19 7.4,19 7.25,18.85 7.25,18.2 U10.4@6.9,17.85 ; R1.2@5.4,18.45 6.35,18.45 6.9,17.9 U10.4@6.9,17.85
  Bottom Layer w0.15: v1(1.729,30.429) 2.008,30.15 5.95,30.15 6.95,29.15 6.95,26.976 7.338,26.588 X6.15@8.8,26.588
IN_P: IN+.1 R1.1 R21.2 U10.3 X6.17 | length 34.7
  Top Layer w0.15: v1(2.259,30.959) 2.259,30.323 2.9,29.682 2.9,20.5 4.25,19.15 5,19.15 R1.1@5.4,19.55 ; IN+.1@4.6,20.4 5.4,19.6 R1.1@5.4,19.55 ; U10.3@6.9,20.3 U10.3@6.9,20.1 ; R21.2@10.25,13.7 8.15,15.8 8.15,18.832 7.275,19.707 7.275,19.725 U10.3@6.9,20.1 ; R1.1@5.4,19.55 6.35,19.55 U10.3@6.9,20.1
  Bottom Layer w0.15: v1(2.259,30.959) 2.259,30.541 2.35,30.45 6.074,30.45 7.25,29.274 7.25,27.1 7.462,26.888 7.59,26.888 7.925,27.223 X6.17@8.8,27.223
LD1: V1.2 V2.1
  other v1: 36.444,29.059 37.244,29.059 38.044,29.059 38.844,29.059 36.044,29.859 36.844,29.859 37.644,29.859 38.444,29.859 39.244,29.859 40.044,29.859 36.444,30.659 37.244,30.659 38.044,30.659 38.844,30.659 39.644,30.659 40.444,30.659 36.844,31.459 37.644,31.459 38.444,31.459 39.244,31.459 40.044,31.459 40.844,31.459 41.644,31.459 36.444,32.259 37.244,32.259 38.044,32.259 38.844,32.259 39.644,32.259 40.444,32.259 41.244,32.259 42.044,32.259 36.844,33.059 37.644,33.059 38.444,33.059 39.244,33.059 40.044,33.059 40.844,33.059 41.644,33.059 42.444,33.059 43.244,33.059 44.044,33.059 44.844,33.059 45.644,33.059 46.444,33.059 47.244,33.059 48.044,33.059 48.844,33.059 49.644,33.059 50.444,33.059 51.244,33.059 52.044,33.059 52.844,33.059 53.644,33.059 36.444,33.859 37.244,33.859 38.044,33.859 38.844,33.859 39.644,33.859 40.444,33.859 41.244,33.859 42.044,33.859 42.844,33.859 43.644,33.859 44.444,33.859 45.244,33.859 46.044,33.859 46.844,33.859 47.644,33.859 48.444,33.859 49.244,33.859 50.044,33.859 50.844,33.859 51.644,33.859 52.444,33.859 53.244,33.859 54.044,33.859 36.844,34.659 37.644,34.659 38.444,34.659 39.244,34.659 40.044,34.659 40.844,34.659 41.644,34.659 42.444,34.659 43.244,34.659 44.044,34.659 44.844,34.659 45.644,34.659 46.444,34.659 47.244,34.659 48.044,34.659 48.844,34.659 49.644,34.659 50.444,34.659 51.244,34.659 52.044,34.659 52.844,34.659 53.644,34.659 54.444,34.659 55.244,34.659 38.044,35.459 38.844,35.459 39.644,35.459 40.444,35.459 41.244,35.459 42.044,35.459 42.844,35.459 43.644,35.459 44.444,35.459 45.244,35.459 46.044,35.459 46.844,35.459 47.644,35.459 48.444,35.459 49.244,35.459 50.044,35.459 50.844,35.459 51.644,35.459 52.444,35.459 53.244,35.459 54.044,35.459 54.844,35.459 55.644,35.459 38.444,36.259 39.244,36.259 40.044,36.259 40.844,36.259 41.644,36.259 42.444,36.259 43.244,36.259 44.044,36.259 44.844,36.259 45.644,36.259 46.444,36.259 47.244,36.259 48.044,36.259 48.844,36.259 49.644,36.259 50.444,36.259 51.244,36.259 52.044,36.259 52.844,36.259 53.644,36.259 54.444,36.259 55.244,36.259 56.044,36.259 56.844,36.259 39.644,37.059 40.444,37.059 41.244,37.059 42.044,37.059 42.844,37.059 43.644,37.059 44.444,37.059 45.244,37.059 46.044,37.059 46.844,37.059 47.644,37.059 48.444,37.059 49.244,37.059 50.044,37.059 50.844,37.059 51.644,37.059 52.444,37.059 53.244,37.059 54.044,37.059 54.844,37.059 55.644,37.059 56.444,37.059 57.244,37.059 58.044,37.059 48.044,37.859 48.844,37.859 49.644,37.859 50.444,37.859 51.244,37.859 52.044,37.859 52.844,37.859 53.644,37.859 54.444,37.859 55.244,37.859 56.044,37.859 56.844,37.859 57.644,37.859 58.444,37.859 59.244,37.859 60.044,37.859 49.244,38.659 50.044,38.659 50.844,38.659 51.644,38.659 52.444,38.659 53.244,38.659 54.044,38.659 54.844,38.659 55.644,38.659 56.444,38.659 57.244,38.659 58.044,38.659 58.844,38.659 59.644,38.659 60.444,38.659 61.244,38.659 49.644,39.459 50.444,39.459 51.244,39.459 52.044,39.459 52.844,39.459 53.644,39.459 54.444,39.459 55.244,39.459 56.044,39.459 56.844,39.459 57.644,39.459 58.444,39.459 59.244,39.459 60.044,39.459 60.844,39.459 61.644,39.459 50.844,40.259 51.644,40.259 52.444,40.259 53.244,40.259 54.044,40.259 54.844,40.259 55.644,40.259 56.444,40.259 57.244,40.259 58.044,40.259 58.844,40.259 59.644,40.259 60.444,40.259 61.244,40.259 51.244,41.059 52.044,41.059 52.844,41.059 53.644,41.059 54.444,41.059 55.244,41.059 56.044,41.059 56.844,41.059 57.644,41.059 58.444,41.059 59.244,41.059 60.044,41.059 60.844,41.059 61.644,41.059 52.444,41.859 53.244,41.859 54.044,41.859 54.844,41.859 55.644,41.859 56.444,41.859 57.244,41.859 58.044,41.859 58.844,41.859 59.644,41.859 60.444,41.859 61.244,41.859 52.844,42.659 53.644,42.659 54.444,42.659 55.244,42.659 56.044,42.659 56.844,42.659 57.644,42.659 58.444,42.659 59.244,42.659 60.044,42.659 60.844,42.659 61.644,42.659 54.044,43.459 54.844,43.459 55.644,43.459 56.444,43.459 57.244,43.459 58.044,43.459 58.844,43.459 59.644,43.459 60.444,43.459 61.244,43.459
LD2: V2.2 V3.1
  other v1: 43.644,18.659 44.444,18.659 45.244,18.659 46.044,18.659 46.844,18.659 47.644,18.659 48.444,18.659 49.244,18.659 50.044,18.659 50.844,18.659 51.644,18.659 52.444,18.659 42.444,19.459 43.244,19.459 44.044,19.459 44.844,19.459 45.644,19.459 46.444,19.459 47.244,19.459 48.044,19.459 48.844,19.459 49.644,19.459 50.444,19.459 51.244,19.459 52.044,19.459 42.044,20.259 42.844,20.259 43.644,20.259 44.444,20.259 45.244,20.259 46.044,20.259 46.844,20.259 47.644,20.259 48.444,20.259 49.244,20.259 50.044,20.259 50.844,20.259 51.644,20.259 40.844,21.059 41.644,21.059 42.444,21.059 43.244,21.059 44.044,21.059 44.844,21.059 45.644,21.059 46.444,21.059 47.244,21.059 48.044,21.059 48.844,21.059 49.644,21.059 50.444,21.059 51.244,21.059 40.444,21.859 41.244,21.859 42.044,21.859 42.844,21.859 43.644,21.859 44.444,21.859 45.244,21.859 46.044,21.859 46.844,21.859 47.644,21.859 48.444,21.859 49.244,21.859 50.044,21.859 50.844,21.859 51.644,21.859 39.244,22.659 40.044,22.659 40.844,22.659 41.644,22.659 42.444,22.659 43.244,22.659 44.044,22.659 44.844,22.659 45.644,22.659 46.444,22.659 47.244,22.659 48.044,22.659 48.844,22.659 49.644,22.659 50.444,22.659 51.244,22.659 30.844,23.459 31.644,23.459 36.444,23.459 37.244,23.459 38.044,23.459 38.844,23.459 39.644,23.459 40.444,23.459 41.244,23.459 42.044,23.459 42.844,23.459 43.644,23.459 44.444,23.459 45.244,23.459 46.044,23.459 46.844,23.459 47.644,23.459 48.444,23.459 49.244,23.459 50.044,23.459 50.844,23.459 30.444,24.259 31.244,24.259 36.844,24.259 37.644,24.259 38.444,24.259 39.244,24.259 40.044,24.259 40.844,24.259 41.644,24.259 42.444,24.259 43.244,24.259 44.044,24.259 44.844,24.259 45.644,24.259 46.444,24.259 47.244,24.259 48.044,24.259 48.844,24.259 49.644,24.259 50.444,24.259 51.244,24.259 29.244,25.059 30.044,25.059 30.844,25.059 31.644,25.059 32.444,25.059 36.444,25.059 37.244,25.059 38.044,25.059 38.844,25.059 39.644,25.059 40.444,25.059 41.244,25.059 42.044,25.059 42.844,25.059 43.644,25.059 44.444,25.059 45.244,25.059 46.044,25.059 46.844,25.059 47.644,25.059 48.444,25.059 49.244,25.059 50.044,25.059 50.844,25.059 29.644,25.859 30.444,25.859 31.244,25.859 36.844,25.859 37.644,25.859 38.444,25.859 39.244,25.859 40.044,25.859 40.844,25.859 41.644,25.859 42.444,25.859 43.244,25.859 44.044,25.859 44.844,25.859 45.644,25.859 46.444,25.859 47.244,25.859 48.044,25.859 48.844,25.859 49.644,25.859 50.444,25.859 51.244,25.859 29.244,26.659 30.044,26.659 30.844,26.659 31.644,26.659 36.444,26.659 37.244,26.659 38.044,26.659 38.844,26.659 39.644,26.659 40.444,26.659 41.244,26.659 42.044,26.659 42.844,26.659 43.644,26.659 44.444,26.659 45.244,26.659 46.044,26.659 46.844,26.659 47.644,26.659 48.444,26.659 49.244,26.659 50.044,26.659 50.844,26.659 29.644,27.459 30.444,27.459 31.244,27.459 36.844,27.459 37.644,27.459 38.444,27.459 39.244,27.459 40.044,27.459 40.844,27.459 41.644,27.459 42.444,27.459 43.244,27.459 44.044,27.459 44.844,27.459 45.644,27.459 46.444,27.459 47.244,27.459 48.044,27.459 48.844,27.459 49.644,27.459 50.444,27.459 51.244,27.459 30.844,28.259 31.644,28.259 40.444,28.259 41.244,28.259 42.044,28.259 42.844,28.259 43.644,28.259 44.444,28.259 45.244,28.259 46.044,28.259 46.844,28.259 47.644,28.259 48.444,28.259 49.244,28.259 50.044,28.259 50.844,28.259 51.644,28.259 31.644,29.059 40.844,29.059 41.644,29.059 42.444,29.059 43.244,29.059 44.044,29.059 44.844,29.059 45.644,29.059 46.444,29.059 47.244,29.059 48.044,29.059 48.844,29.059 49.644,29.059 50.444,29.059 51.244,29.059 42.044,29.859 42.844,29.859 43.644,29.859 44.444,29.859 45.244,29.859 46.044,29.859 46.844,29.859 47.644,29.859 48.444,29.859 49.244,29.859 50.044,29.859 50.844,29.859 51.644,29.859 42.444,30.659 43.244,30.659 44.044,30.659 44.844,30.659 45.644,30.659 46.444,30.659 47.244,30.659 48.044,30.659 48.844,30.659 49.644,30.659 50.444,30.659 51.244,30.659 52.044,30.659 43.644,31.459 44.444,31.459 45.244,31.459 46.044,31.459 46.844,31.459 47.644,31.459 48.444,31.459 49.244,31.459 50.044,31.459 50.844,31.459 51.644,31.459 52.444,31.459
